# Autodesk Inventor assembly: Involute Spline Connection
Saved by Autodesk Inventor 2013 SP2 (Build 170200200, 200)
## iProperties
Created: 2020-02
Part Number: Involute Spline Connection
Document SubType Name: Assembly
Designer: DELL
ClientObjectVersion: 1
Author: DELL
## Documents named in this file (1)
- C:\Users\DELL\Dropbox\Inventor\Projects\Quadcopter F450\Assemblies\Servo - Design Accelerator Spline Tutorial\Design Accelerator\Involute Spline Connection2.iam
